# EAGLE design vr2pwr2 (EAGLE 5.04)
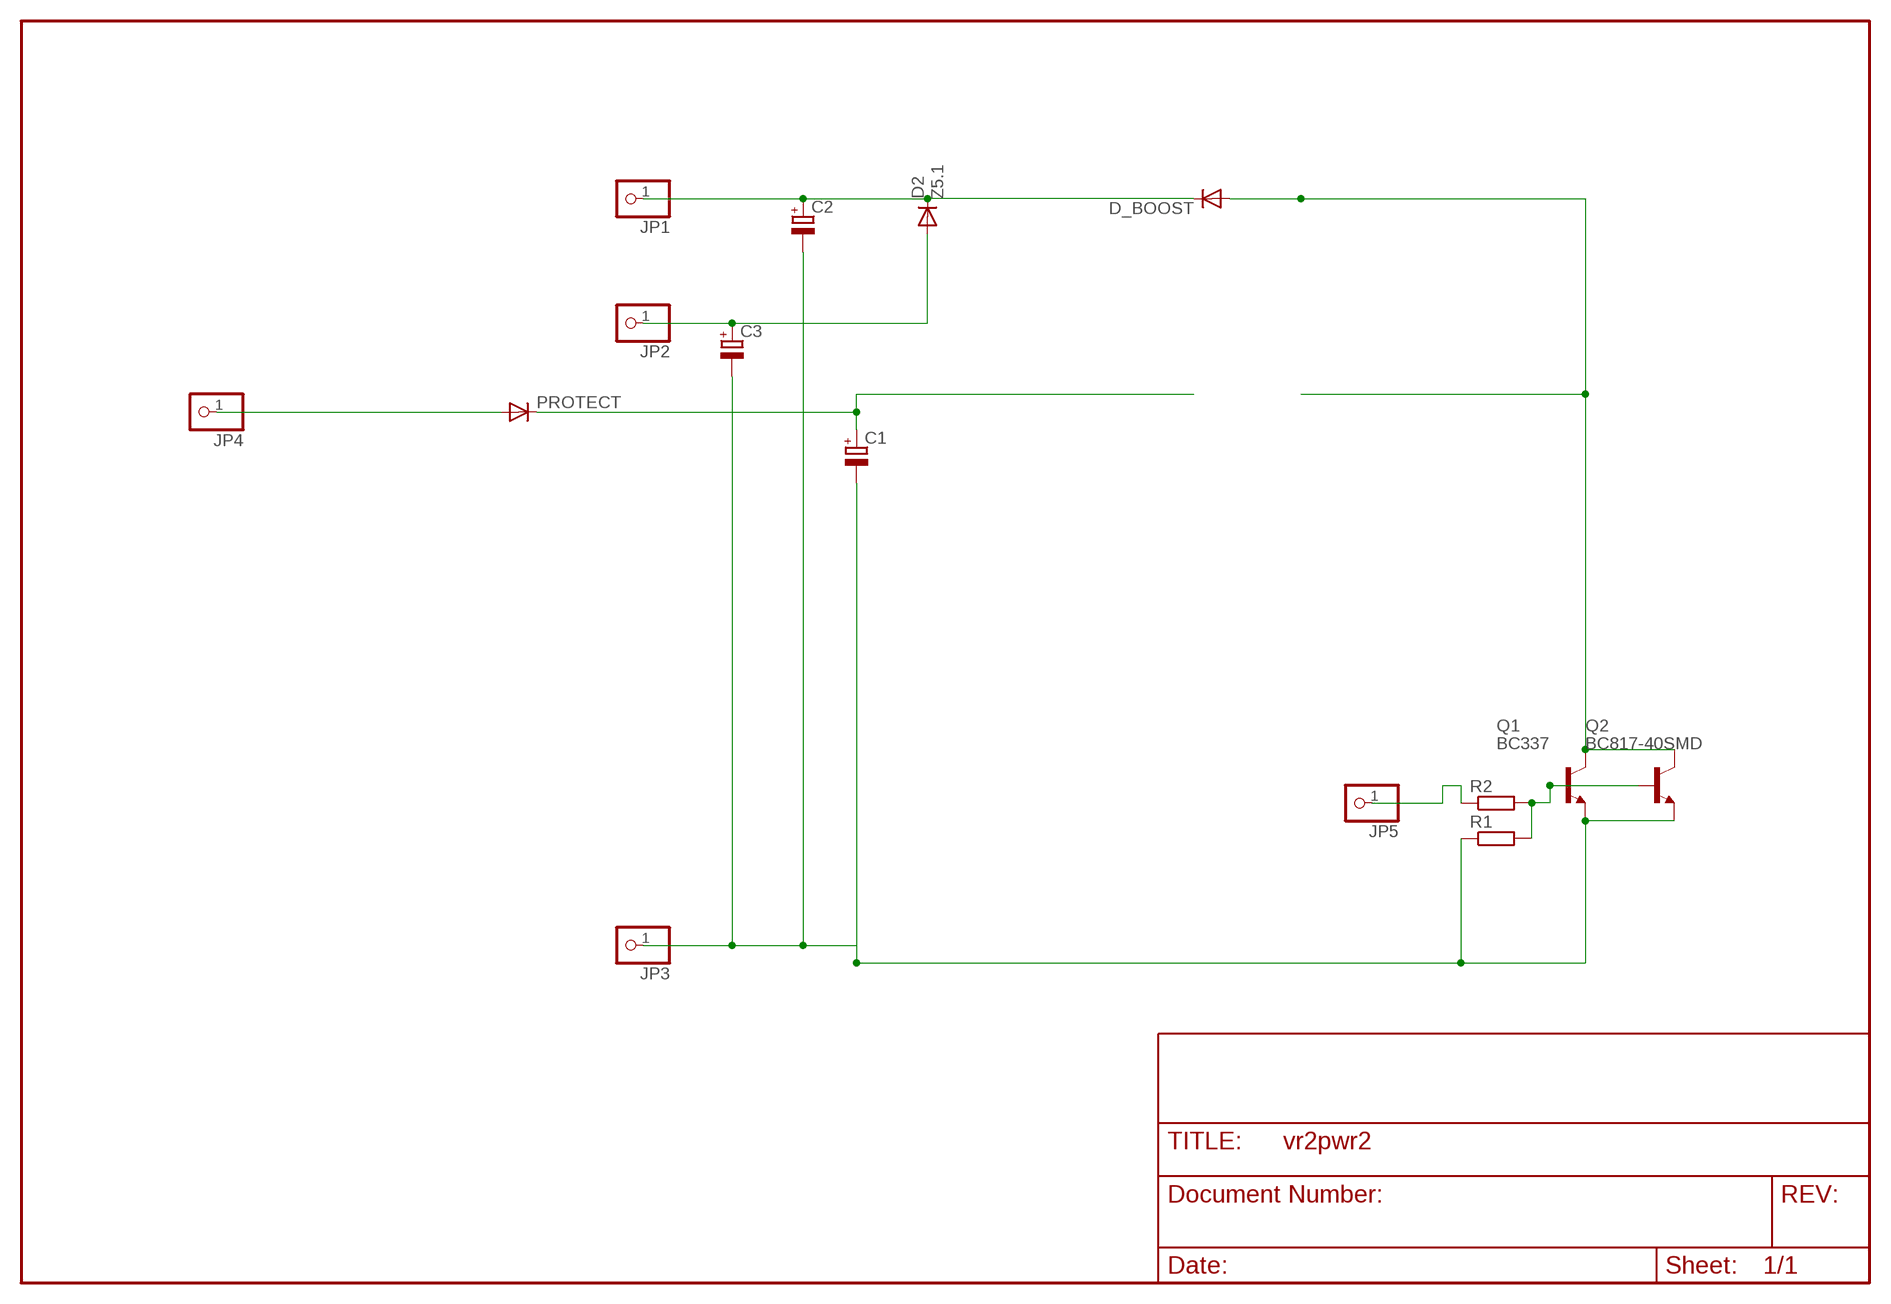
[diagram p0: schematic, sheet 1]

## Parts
C1  CPOL-EUE2.5-7  [E2,5-7]
C2  CPOL-EUE2.5-7  [E2,5-7]
C3  CPOL-EUE2-4  [E2-4]
D2  Z5.1  DIODE-D-2.5  [D-2.5]
D_BOOST  DIODE-D-5  [D-5]
JP1  PINHD-1X1  [1X01]
JP2  PINHD-1X1  [1X01]
JP3  PINHD-1X1  [1X01]
JP4  PINHD-1X1  [1X01]
JP5  PINHD-1X1  [1X01]
PROTECT  DIODE-D-5  [D-5]
Q1  BC337  [TO92]
Q2  BC817-40SMD  [SOT23-BEC]
R1  R-EU_R1206  [R1206]
R2  R-EU_R1206  [R1206]

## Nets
GND: C1.- C2.- C3.- JP3.1 Q1.1(E) Q2.E R1.1
HOTSPOT: D_BOOST.A Q1.3(C) Q2.C
LOAD: C2.+ D2.C D_BOOST.C JP1.1
N$1: Q1.2(B) Q2.B R1.2 R2.2
N$2: C1.+ PROTECT.C
N$3: JP5.1 R2.1
N$4: C3.+ D2.A JP2.1
N$6: JP4.1 PROTECT.A

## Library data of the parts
C1-C3 = rcl(2):CPOL-EU: POLARIZED CAPACITOR, European symbol
D2 D_BOOST PROTECT = diode:DIODE-: DIODE
JP1-JP5 = pinhead:PINHD-1X1: PIN HEADER
Q1 = transistor-npn:BC337*: NPN Transistor
Q2 = transistor-npn:BC817*: NPN Transistor
R1 R2 = rcl-2:R-EU_: RESISTOR, European symbol

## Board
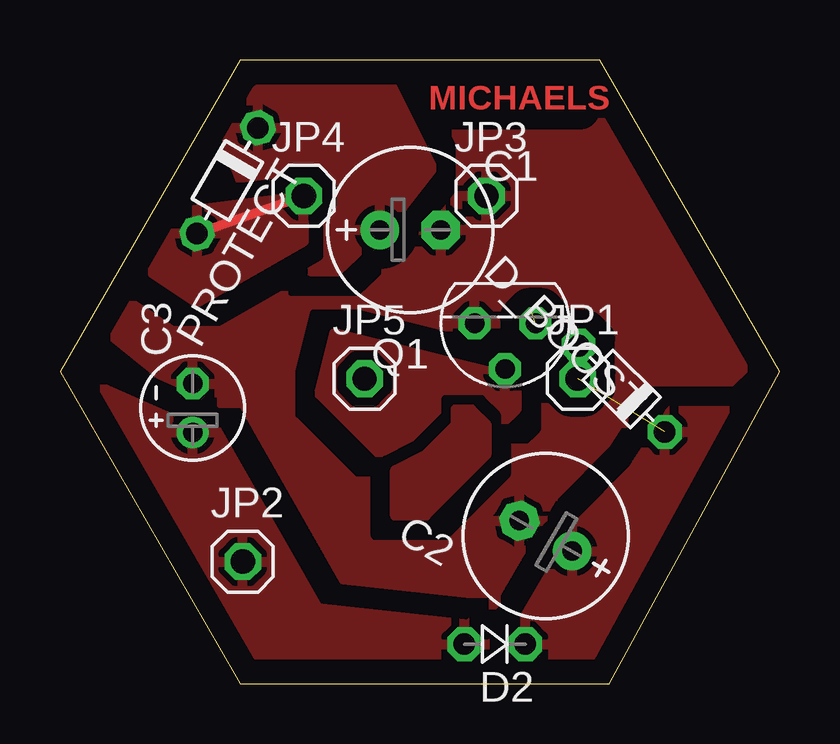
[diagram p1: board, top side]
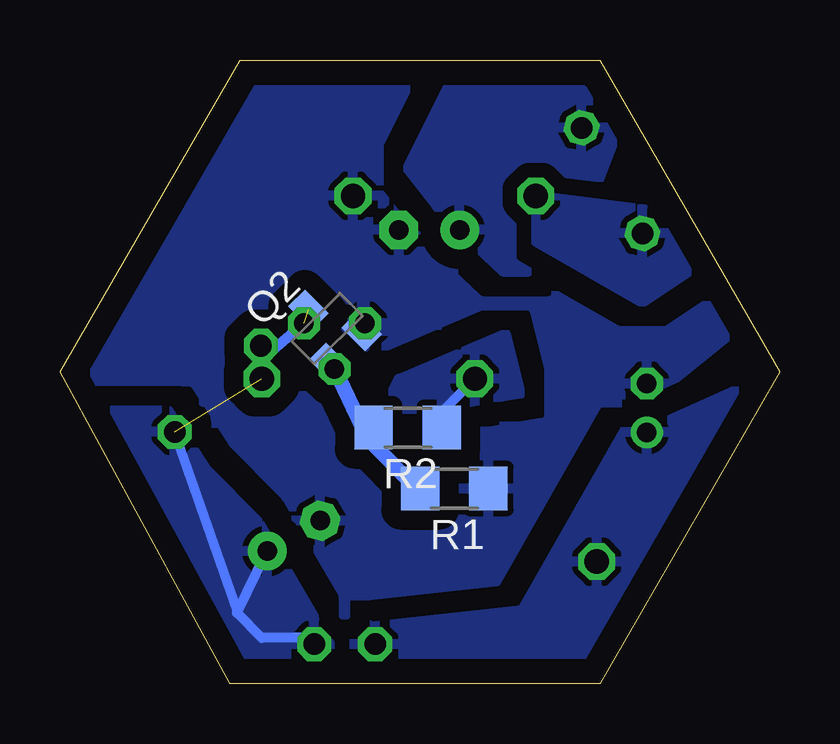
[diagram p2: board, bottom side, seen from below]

Size 30 x 25.98 mm. Coordinates in mm from the lower left corner, seen from the top.
Outline: 7.5,0 22.9,0 30,12.99 22.5,25.98 7.5,25.98 0,12.99 7.5,0
Copper layers (1*16): Top 0.035mm / dielectric 1.5mm / Bottom 0.035mm
Design rules "default": minimum track width 10mil, minimum drill 24mil, track to track 8mil, track to pad 8mil, pad to pad 8mil, via to via 8mil, smd to smd 8mil, copper to edge 40mil, drill to drill 8mil, minimum pad ring 10mil, minimum via ring 8mil, stop-mask expansion 4mil, vias tented up to drill 0mil, thermal gap 10mil

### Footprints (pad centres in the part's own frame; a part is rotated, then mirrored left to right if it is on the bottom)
E2,5-7 = drill 0.813 pad 1.6 round: + -1.27,0 | drill 0.813 pad 1.6 octagon: - 1.27,0
E2-4 = drill 0.813 pad 1.27 round: + -1.016,0 | drill 0.813 pad 1.27 octagon: - 1.016,0
D-2.5 = drill 0.9 octagon: A 1.27,0; C -1.27,0
D-5 = drill 0.9 octagon: A 2.54,0; C -2.54,0
1X01 = drill 1.016 octagon: 1 0,0
TO92 = drill 0.813 octagon: 1 1.27,0; 2 0,1.905; 3 -1.27,0
SOT23-BEC = smd 1 x 1.4: B -0.95,-1.1; C 0,1.1; E 0.95,-1.1
R1206 = smd 1.6 x 1.803: 1 -1.422,0; 2 1.422,0

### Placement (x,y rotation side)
C1  14.61,18.9 0 top
C2  20.25,6.15 150 top
C3  5.53,11.48 90 top
D2  18.13,1.64 180 top
D_BOOST  23.42,12.28 135 top
JP1  21.59,12.7 0 top
JP2  7.62,5.08 0 top
JP3  17.78,20.32 0 top
JP4  10.16,20.32 0 top
JP5  12.7,12.7 0 top
PROTECT  6.99,20.95 240 top
Q1  18.55,15.01 180 top
Q2  18.86,14.79 45 bottom
R1  13.56,8.12 180 bottom
R2  15.51,10.66 180 bottom

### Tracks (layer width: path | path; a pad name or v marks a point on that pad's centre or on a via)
GND
  Bottom 0.406: Q2.E 17.41,14.88 Q1.1
  pour Bottom (isolate 0.813, rank 3): 0.9,15.5 6.87,26.73 22.5,26.09 30.2,14.7 22.53,0.32 11.64,2.16 6.64,10.86
  pour Top (isolate 0.813, rank 3): 0.9,15.5 7.5,28 22.5,28 30.2,14.7 14.18,-0.38 6.64,10.86
HOTSPOT  (1 unrouted)
  Bottom 0.406: Q1.3 21.29,13.74 D_BOOST.A
LOAD  (1 unrouted)
  Bottom 0.406: 22.62,2.94 C2.+ | D2.C 19.66,1.91 21.59,1.91 22.62,2.94 | 22.62,2.94 22.62,3.06 D_BOOST.C
  pour Bottom (isolate 0.61): 18.74,1.66 21.71,6.74 23.91,8.94 25.48,11.38 28.91,11.38 25.27,6.13 24,1.36 18.84,-0.54
  pour Top (isolate 0.61): 18.74,1.66 21.71,6.74 23.91,8.94 25.48,11.38 28.91,11.38 25.27,6.13 24,1.36 18.84,-0.54
N$1
  Bottom 0.406: R1.2 15.11,8.12 | 17.14,10.16 17.14,10.45 R2.2 17.38,10.66 | Q1.2 18.55,13.14 Q2.B
  Bottom 0.61: 15.11,8.12 17.14,10.16 | 17.38,10.66 Q1.2
  pour Top (isolate 0.406, rank 2): 11.43,14.61 10.79,12.06 13.34,9.53 18.41,10.79 19.05,11.43 19.05,12.7
N$2
  pour Bottom (isolate 0.61, rank 2): 11.54,17.16 10.47,17.16 8.44,18.57 6.54,23.53 8.8,25.16 13.71,25.16 15.54,21.46 14.27,19.84 12.6,18.16
  pour Top (isolate 0.61, rank 2): 11.54,17.16 10.47,17.16 8.44,18.57 6.54,23.53 8.8,25.16 13.71,25.16 15.54,21.46 14.27,19.84 12.6,18.16
N$3
  Bottom 0.406: R2.1 14.08,11.32 JP5.1
  pour Bottom (isolate 0.406): 11.43,14.61 10.79,12.06 14.61,11.43 16.51,11.43 15.88,12.7
N$4
  pour Bottom (isolate 0.61, rank 2): 17.14,2.46 17.34,2.46 17.74,2.06 17.74,-0.54 15.63,-0.1 8.04,-0.1 1.4,12.4 4.84,10.86 6.34,10.76 10.74,3.06 17.04,2.36
  pour Top (isolate 0.61, rank 2): 17.14,2.56 17.34,2.56 17.74,2.16 17.74,-0.44 15,-0.01 7.4,-0.01 1.4,12.5 4.84,10.96 6.34,10.86 10.74,3.16 17.04,2.46
N$5
  pour Top (isolate 0.406): 13.97,8.89 15.24,9.53 16.51,10.79 16.51,11.43 17.14,11.43 17.78,10.79 17.78,9.53 15.24,6.99 13.97,6.99
N$6
  Top 0.406: PROTECT.A JP4.1
  pour Top: 10.16,20.32 10.16,18.41 5.71,15.88 3.81,17.14 5.08,19.68
  pour Bottom: 10.16,20.32 10.16,18.41 5.71,15.88 3.81,17.14 5.08,19.68

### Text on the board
Top: MICHAELS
